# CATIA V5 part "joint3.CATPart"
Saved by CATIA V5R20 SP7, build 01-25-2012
Part number: joint3
Bounding box of the stored display mesh (mm): x 300 to 491, y -23 to 23, z 473.014 to 523.014
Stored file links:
  D:\thinkmotion-MPB\Dropbox\Pack 1 sylvain\CFAO_2010_yyang\yyang\CFAO_2010_yyang\joint3.CATPart
  D:\thinkmotion-MPB\Dropbox\Pack 1 sylvain\CFAO_2010_yyang\yyang\CFAO_2010_yyang\yyang.CATProduct
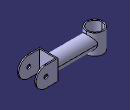
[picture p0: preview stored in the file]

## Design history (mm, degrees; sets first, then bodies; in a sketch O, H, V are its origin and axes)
External parameters (linked from other documents)
  `External.hauteur du pivot plus haut` = 375 mm
  `External.longeur du tube` = 350 mm
  `External.longueur du pivoty` = 30 mm
  `External.epaisseur du pivoty` = 3 mm
  `External.epaisseur du pivot` = 2 mm
  `External.demi_distance entre les oreilles` = 15 mm
  `External.epaisseur de l'oreille` = 3 mm
  `External.rayon du trou des liaisons` = 5 mm
  `External.rayon1 du pivotz` = 18 mm
  `External.rayon2 du pivotz` = 21 mm
  `External.demi_hauteur du pivotz` = 25 mm
  `External.rayon exterieur du lien` = 18 mm
  `External.rayon interieur du lien` = 16 mm
Set1
  Plane1: linked copy from another document
  Point1: linked copy from another document
  Plane2: linked copy from another document
  Point2: linked copy from another document
Body1 (main body)
  Sketch1 on Plane1, origin (0, 0, 0), H (-1, 0, 0), V (0, 0, 1)
    arc A1 centre (-466, 498.0139) radius 25 from (-466, 523.0139) to (-466, 473.0139) ccw
    point P1 (-466, 498.0139)
    reference projected point E1 (-466, 498.0139) from Point1
    reference projected point E2 (-466, 498.0139) from Point1
    line L1 (-466, 523.0139) -> (-436, 523.0139)
    line L2 (-436, 523.0139) -> (-436, 473.0139)
    line L3 (-436, 473.0139) -> (-466, 473.0139)
    reference projected point E3 (-466, 498.0139) from Point1
    circle A2 centre (-466, 498.0139) radius 5
    point P6 (-466, 498.0139)
    reference projected point E4 (-466, 498.0139) from Point1
    reference projected point E5 (-466, 498.0139) from Point1
    distance A1 E2 = 25 {= `External.hauteur du pivot plus haut`-`External.longeur du tube`}
    distance L2 E3 = 30 {= `External.longueur du pivoty`}
    distance A2 E5 = 5 {= `External.rayon du trou des liaisons`}
    coincidence: P1 E1, P6 E4
    horizontal: L1 H, L3 H
    vertical: L2 V
    tangency: L3 A1, L1 A1
  Pad1: profile Sketch1, direction (0, 1, 0), length 23 {= `External.epaisseur du pivoty`+`External.epaisseur du pivot`+`External.demi_distance entre les oreilles`+`External.epaisseur de l'oreille`}, mirrored extent
  Sketch2 on Plane1, origin (0, 0, 0), H (-1, 0, 0), V (0, 0, 1)
    line L1 (-491, 523.0139) -> (-439, 523.0139)
    line L2 (-439, 523.0139) -> (-439, 473.0139)
    line L3 (-439, 473.0139) -> (-491, 473.0139)
    line L4 (-491, 473.0139) -> (-491, 523.0139)
    reference projected arc E1 centre (-466, 498.0139) radius 25 from (-466, 523.0139) to (-466, 473.0139) ccw from edge [face of Pad1 from Sketch1.A1 | end face of Pad1]
    reference projected line E2 (-466, 473.0139) -> (-436, 473.0139) from edge [face of Pad1 from Sketch1.L3 | end face of Pad1]
    reference projected line E3 (-436, 523.0139) -> (-466, 523.0139) from edge [face of Pad1 from Sketch1.L1 | end face of Pad1]
    reference projected line E4 (-436, 473.0139) -> (-436, 523.0139) from edge [face of Pad1 from Sketch1.L2 | end face of Pad1]
    distance L2 E4 = 3 {= `External.epaisseur du pivoty`}
    horizontal: L1 H, L3 H
    vertical: L2 V, L4 V
    tangency: L4 E1
    coincidence: L3 E2, L1 E3
  Pocket1: profile Sketch2, direction (0, -1, 0), length 20 {= `External.demi_distance entre les oreilles`+`External.epaisseur de l'oreille`+`External.epaisseur du pivot`}, mirrored extent
  Sketch3 on Plane2, origin (0, 0, 498.0139), H (1, 0, 0), V (0, 1, 0)
    circle A1 centre (321, 0) radius 18
    point P1 (321, 0)
    reference projected point E1 (321, 0) from Point2
    reference projected point E2 (321, 0) from Point2
    circle A2 centre (321, 0) radius 21
    point P2 (321, 0)
    reference projected point E3 (321, 0) from Point2
    reference projected point E4 (321, 0) from Point2
    distance A1 E2 = 18 {= `External.rayon1 du pivotz`}
    distance A2 E4 = 21 {= `External.rayon2 du pivotz`}
    coincidence: P1 E1, P2 E3
  Pad2: profile Sketch3, direction (0, 0, 1), length 25 {= `External.demi_hauteur du pivotz`}, mirrored extent
  Sketch4 on face of Pad1 from Sketch1.L2, origin (436, 0, 0), H (0, -1, 0), V (0, 0, 1)
    circle A1 centre (0, 498.0139) radius 18
    point P1 (0, 498.0139)
    reference projected point E1 (0, 498.0139) from Point1
    reference projected point E2 (0, 498.0139) from Point1
    circle A2 centre (0, 498.0139) radius 16
    point P2 (0, 498.0139)
    reference projected point E3 (0, 498.0139) from Point1
    reference projected point E4 (0, 498.0139) from Point1
    distance A1 E2 = 18 {= `External.rayon exterieur du lien`}
    distance A2 E4 = 16 {= `External.rayon interieur du lien`}
    coincidence: P1 E1, P2 E3
  Pad3: profile Sketch4, direction (-1, 0, 0), up to face of Pad2 from Sketch3.A2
